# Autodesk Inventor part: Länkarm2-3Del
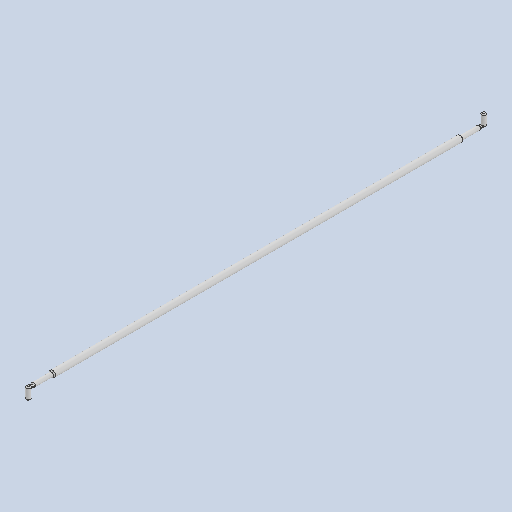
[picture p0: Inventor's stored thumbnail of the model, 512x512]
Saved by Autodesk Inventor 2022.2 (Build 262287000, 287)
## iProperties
Created: 2022-03
Part Number: Länkarm2-3Del
Material: Generic
Document SubType Name: Modeling
Designer: cl
Density: 1 g/cm^3
Appearance: Default
Author: cl
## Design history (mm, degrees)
sketch "Sketch1"
  geometry: L1 (0, 0)-(0, -2128.16); L2 (0, 0)-(-10, 0); L3 (-10, 0)-(-10, -90); L4 (-10, -90)-(-15, -90); L5 (-15, -90)-(-15, -2038.16); L6 (0, -2128.16)-(-10, -2128.16); L7 (-10, -2128.16)-(-10, -2038.16); L8 (-10, -2038.16)-(-15, -2038.16); 1 further point
  constraints: 16 end point, 5 perpendicular, 2 horizontal, 1 midpoint, 1 vertical
  dimensions: "d0" = 2128.16 distance of L1.start L1.end (computed from BladBredd); "d1" = 20 diameter of L3 L1; "d2" = 5 distance between parallel lines of L3 L5; "d3" = 90 distance of L2.end L3.end; "d4" = 20 diameter of L7 L1; "d5" = 90 vertical distance of point (-5, -2128.16) L5.end
revolve "Revolution1" sketch "Sketch1" stored, may be unused: angle "d6" = 90 deg
fillet "Fillet1" dims "d7" = 5
workplane "Work Plane1"
sketch "Sketch2"
  geometry: L1 (10, 0)-(-10, 0) reference; L2 (7.5, 0)-(-7.5, 0); L3 (-7.5, 0)-(-7.5, 20); L4 (-7.5, 20)-(7.5, 20); L5 (7.5, 20)-(7.5, 0); L6 (10, -90)-(10, 0) reference; L7 (10, -2128.16)-(-10, -2128.16) reference; L8 (7.5, -2128.16)-(-7.5, -2128.16); L9 (-7.5, -2128.16)-(-7.5, -2148.16); L10 (-7.5, -2148.16)-(7.5, -2148.16); L11 (7.5, -2148.16)-(7.5, -2128.16); 3 further points
  constraints: 16 end point, 4 parallel, 2 horizontal, 2 perpendicular, 2 point on line, 1 collinear
  dimensions: "d9" = 2.5 distance between parallel lines of L5 L6; "d10" = 15 distance of L3.end L4.end; "d11" = 20 distance of L2.end L3.end; "d12" = 20 distance of L8.end L9.end; "d13" = 15 distance of L9.end L10.end
extrude "Extrusion1" join sketch "Sketch2" distance "d14" = 4; taper "d15" = 0 deg
sketch "Sketch3"
  geometry: L1 (7.5, 20)-(-7.5, 20) reference; L2 (-7.5, -2148.16)-(7.5, -2148.16) reference; C1 r 10 at (0, 20); C2 r 10 at (0, -2148.16); 1 further point
  constraints: 2 centre point, 2 midpoint
  dimensions: "d16" = 20 diameter of C1; "d17" = 20 diameter of C2
extrude "Extrusion2" join sketch "Sketch3" distance "d18" = 8; taper "d20" = 0 deg; dims "d19" = 48, "d21" = 0
extrude "Extrusion3" join sketch "Sketch3" distance "d22" = 50; taper "d24" = 0 deg; dims "d23" = 6, "d25" = 0
fillet "Fillet2" dims "d26" = 5
body "Solid1"
other parameters: "BladBredd" = 1333.33333, "Fönsterhöjd" = 862, "Blad2" = 1358.33333, "Blad3" = 0, "Blad4" = 0, "Blad5" = 0, "Blad6" = 2025, "MGJ12Djup" = 0, "MGJ12Bredd" = 0, "MGJ2Djup" = 0, "MGJ2Bredd" = 5012.5, "MGJ56Djup" = 48, "MGJ23Djup" = 48, "MGJ45Djup" = 48, "GarageRegel5" = 0, "GarageRegel6" = 0, "StyrskenaV" = 2766.66667, "Styrrulle2Djup" = 48, "FönsterhöjdStyrning" = 862, "FönsterKarm" = 54, "AndraGlasraden" = 0, "BrösthöjdStyrning2" = 0.0001, "InfälldGångDörr" = 0, "Infälldstyr" = 1012.5, "EnDelGångDörr" = 0, "VinkelJärnStyrSkena" = 2666.66667, "d8" = -2
